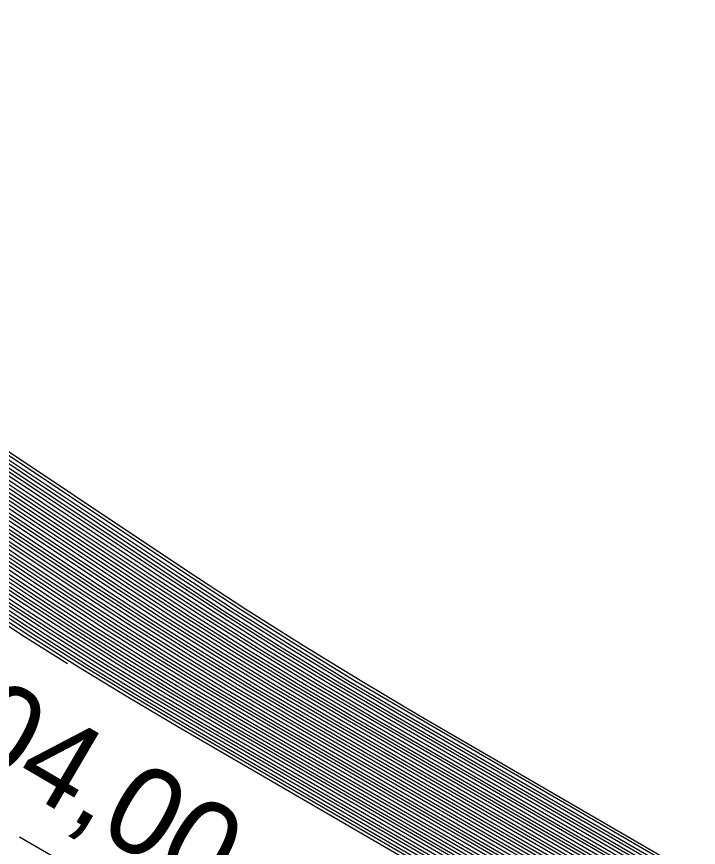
# Model space of a CAD drawing. Extents: x -500397 to -496810, y -1135552 to -1132176.
# Drawn here: x -500370.44 to -500354.9, y -1134753.02 to -1134734.1 of the extents above; entities that cross this region are included whole.
import ezdxf

# ---------------------------------------------------------------- set-up
doc = ezdxf.new("R2010")
doc.units = 0
doc.layers.add('30', color=7, linetype='Continuous')
doc.layers.add('40', color=7, linetype='Continuous')

msp = doc.modelspace()

# ---------------------------------------------------------------- linework, layer by layer
at = {"layer": '30'}
for points in [[(-500380.743, -1134693.182), (-500385.671, -1134735.388), (-500385.641, -1134736.758), (-500385.201, -1134737.849), (-500384.35, -1134738.663), (-500383.089, -1134739.197), (-500377.22, -1134740.779), (-500375.778, -1134741.23), (-500374.387, -1134741.793), (-500373.046, -1134742.468), (-500371.756, -1134743.254), (-500366.516, -1134746.742), (-500365.215, -1134747.594), (-500363.901, -1134748.426), (-500362.574, -1134749.237), (-500361.235, -1134750.028), (-500343.499, -1134760.322)], [(-500343.695, -1134760.29), (-500361.367, -1134750.034), (-500362.701, -1134749.246), (-500364.023, -1134748.437), (-500365.332, -1134747.609), (-500366.628, -1134746.76), (-500371.849, -1134743.284), (-500373.135, -1134742.501), (-500374.471, -1134741.829), (-500375.857, -1134741.268), (-500377.294, -1134740.818), (-500383.141, -1134739.242), (-500384.398, -1134738.71), (-500385.246, -1134737.9), (-500385.684, -1134736.812), (-500385.713, -1134735.447), (-500382.293, -1134706.144)], [(-500382.833, -1134710.461), (-500385.756, -1134735.506), (-500385.727, -1134736.866), (-500385.29, -1134737.95), (-500384.446, -1134738.757), (-500383.193, -1134739.288), (-500377.367, -1134740.858), (-500375.936, -1134741.306), (-500374.555, -1134741.865), (-500373.224, -1134742.534), (-500371.943, -1134743.315), (-500366.741, -1134746.778), (-500365.449, -1134747.623), (-500364.145, -1134748.449), (-500362.828, -1134749.254), (-500361.498, -1134750.04), (-500343.892, -1134760.258)], [(-500344.088, -1134760.227), (-500361.63, -1134750.045), (-500362.955, -1134749.263), (-500364.267, -1134748.46), (-500365.566, -1134747.638), (-500366.853, -1134746.795), (-500372.036, -1134743.345), (-500373.312, -1134742.567), (-500374.638, -1134741.9), (-500376.015, -1134741.343), (-500377.441, -1134740.897), (-500383.245, -1134739.333), (-500384.493, -1134738.804), (-500385.335, -1134738), (-500385.77, -1134736.92), (-500385.799, -1134735.565), (-500383.373, -1134714.779)], [(-500385.839, -1134735.757), (-500385.813, -1134736.974), (-500385.38, -1134738.05), (-500384.541, -1134738.851), (-500383.298, -1134739.378), (-500377.514, -1134740.937), (-500376.094, -1134741.381), (-500374.722, -1134741.936), (-500373.401, -1134742.601), (-500372.13, -1134743.375), (-500366.966, -1134746.813), (-500365.684, -1134747.653), (-500364.389, -1134748.472), (-500363.082, -1134749.272), (-500361.762, -1134750.051), (-500344.284, -1134760.195)], [(-500344.48, -1134760.163), (-500361.894, -1134750.057), (-500363.209, -1134749.28), (-500364.511, -1134748.484), (-500365.801, -1134747.667), (-500367.079, -1134746.831), (-500372.223, -1134743.406), (-500373.49, -1134742.634), (-500374.806, -1134741.972), (-500376.172, -1134741.419), (-500377.588, -1134740.976), (-500383.35, -1134739.423), (-500384.589, -1134738.898), (-500385.424, -1134738.1), (-500385.856, -1134737.028), (-500385.875, -1134736.143)], [(-500344.677, -1134760.132), (-500362.026, -1134750.063), (-500363.335, -1134749.289), (-500364.633, -1134748.495), (-500365.918, -1134747.682), (-500367.191, -1134746.849), (-500372.317, -1134743.436), (-500373.579, -1134742.667), (-500374.89, -1134742.007), (-500376.251, -1134741.457), (-500377.662, -1134741.015), (-500383.402, -1134739.468), (-500384.637, -1134738.945), (-500385.469, -1134738.15), (-500385.899, -1134737.082), (-500385.911, -1134736.529)], [(-500385.947, -1134736.915), (-500385.942, -1134737.136), (-500385.514, -1134738.2), (-500384.684, -1134738.992), (-500383.455, -1134739.513), (-500377.735, -1134741.055), (-500376.33, -1134741.495), (-500374.974, -1134742.043), (-500373.668, -1134742.701), (-500372.41, -1134743.467), (-500367.304, -1134746.866), (-500366.036, -1134747.696), (-500364.755, -1134748.507), (-500363.462, -1134749.298), (-500362.157, -1134750.068), (-500344.873, -1134760.1)], [(-500385.975, -1134737.216), (-500385.558, -1134738.25), (-500384.732, -1134739.04), (-500383.507, -1134739.559), (-500377.809, -1134741.094), (-500376.409, -1134741.532), (-500375.058, -1134742.079), (-500373.756, -1134742.734), (-500372.504, -1134743.497), (-500367.416, -1134746.884), (-500366.153, -1134747.711), (-500364.877, -1134748.519), (-500363.589, -1134749.306), (-500362.289, -1134750.074), (-500345.069, -1134760.068)], [(-500345.265, -1134760.037), (-500362.421, -1134750.08), (-500363.716, -1134749.315), (-500364.999, -1134748.53), (-500366.27, -1134747.726), (-500367.529, -1134746.902), (-500372.597, -1134743.528), (-500373.845, -1134742.767), (-500375.142, -1134742.115), (-500376.488, -1134741.57), (-500377.883, -1134741.134), (-500383.559, -1134739.604), (-500384.78, -1134739.087), (-500385.603, -1134738.3), (-500385.987, -1134737.346)], [(-500386.012, -1134737.608), (-500385.692, -1134738.4), (-500384.875, -1134739.181), (-500383.664, -1134739.694), (-500378.03, -1134741.213), (-500376.646, -1134741.646), (-500375.31, -1134742.186), (-500374.023, -1134742.834), (-500372.784, -1134743.588), (-500367.754, -1134746.937), (-500366.505, -1134747.755), (-500365.243, -1134748.553), (-500363.97, -1134749.332), (-500362.684, -1134750.092), (-500345.658, -1134759.974)], [(-500385.999, -1134737.477), (-500385.647, -1134738.35), (-500384.827, -1134739.134), (-500383.612, -1134739.649), (-500377.956, -1134741.173), (-500376.567, -1134741.608), (-500375.226, -1134742.15), (-500373.934, -1134742.8), (-500372.691, -1134743.558), (-500367.641, -1134746.919), (-500366.387, -1134747.74), (-500365.121, -1134748.542), (-500363.843, -1134749.324), (-500362.553, -1134750.086), (-500345.462, -1134760.005)], [(-500345.854, -1134759.942), (-500362.816, -1134750.097), (-500364.097, -1134749.341), (-500365.365, -1134748.565), (-500366.622, -1134747.77), (-500367.867, -1134746.955), (-500372.878, -1134743.619), (-500374.112, -1134742.867), (-500375.394, -1134742.222), (-500376.725, -1134741.684), (-500378.104, -1134741.252), (-500383.716, -1134739.739), (-500384.923, -1134739.228), (-500385.737, -1134738.45), (-500386.024, -1134737.738)], [(-500346.051, -1134759.91), (-500362.948, -1134750.103), (-500364.224, -1134749.35), (-500365.488, -1134748.577), (-500366.739, -1134747.784), (-500367.979, -1134746.973), (-500372.971, -1134743.649), (-500374.201, -1134742.9), (-500375.478, -1134742.258), (-500376.803, -1134741.721), (-500378.177, -1134741.291), (-500383.768, -1134739.785), (-500384.971, -1134739.275), (-500385.781, -1134738.5), (-500386.036, -1134737.869)], [(-500386.06, -1134738.13), (-500385.87, -1134738.601), (-500385.066, -1134739.369), (-500383.873, -1134739.875), (-500378.324, -1134741.37), (-500376.961, -1134741.797), (-500375.646, -1134742.329), (-500374.378, -1134742.967), (-500373.158, -1134743.71), (-500368.204, -1134747.008), (-500366.974, -1134747.814), (-500365.732, -1134748.6), (-500364.478, -1134749.367), (-500363.211, -1134750.115), (-500346.443, -1134759.847)], [(-500346.247, -1134759.879), (-500363.08, -1134750.109), (-500364.351, -1134749.358), (-500365.61, -1134748.588), (-500366.857, -1134747.799), (-500368.092, -1134746.99), (-500373.065, -1134743.68), (-500374.289, -1134742.934), (-500375.562, -1134742.293), (-500376.882, -1134741.759), (-500378.251, -1134741.331), (-500383.821, -1134739.83), (-500385.018, -1134739.322), (-500385.826, -1134738.551), (-500386.048, -1134737.999)], [(-500346.639, -1134759.815), (-500363.343, -1134750.121), (-500364.604, -1134749.376), (-500365.854, -1134748.611), (-500367.091, -1134747.828), (-500368.317, -1134747.026), (-500373.252, -1134743.741), (-500374.467, -1134743), (-500375.73, -1134742.365), (-500377.04, -1134741.835), (-500378.398, -1134741.41), (-500383.925, -1134739.92), (-500385.114, -1134739.416), (-500385.915, -1134738.651), (-500386.072, -1134738.261)], [(-500386.097, -1134738.522), (-500386.004, -1134738.751), (-500385.209, -1134739.511), (-500384.03, -1134740.01), (-500378.545, -1134741.489), (-500377.198, -1134741.91), (-500375.898, -1134742.436), (-500374.645, -1134743.067), (-500373.439, -1134743.801), (-500368.542, -1134747.061), (-500367.326, -1134747.858), (-500366.098, -1134748.635), (-500364.858, -1134749.393), (-500363.607, -1134750.132), (-500347.032, -1134759.752)], [(-500346.836, -1134759.784), (-500363.475, -1134750.126), (-500364.731, -1134749.384), (-500365.976, -1134748.623), (-500367.208, -1134747.843), (-500368.429, -1134747.044), (-500373.345, -1134743.771), (-500374.556, -1134743.033), (-500375.814, -1134742.401), (-500377.119, -1134741.872), (-500378.472, -1134741.449), (-500383.978, -1134739.965), (-500385.161, -1134739.464), (-500385.96, -1134738.701), (-500386.084, -1134738.391)], [(-500386.109, -1134738.652), (-500386.049, -1134738.801), (-500385.257, -1134739.558), (-500384.082, -1134740.056), (-500378.619, -1134741.528), (-500377.277, -1134741.948), (-500375.982, -1134742.472), (-500374.733, -1134743.1), (-500373.532, -1134743.832), (-500368.654, -1134747.079), (-500367.443, -1134747.872), (-500366.22, -1134748.646), (-500364.985, -1134749.402), (-500363.738, -1134750.138), (-500347.228, -1134759.72)], [(-500347.621, -1134759.657), (-500364.002, -1134750.15), (-500365.239, -1134749.419), (-500366.464, -1134748.67), (-500367.678, -1134747.901), (-500368.88, -1134747.115), (-500373.719, -1134743.893), (-500374.911, -1134743.167), (-500376.149, -1134742.543), (-500377.434, -1134742.024), (-500378.766, -1134741.607), (-500384.187, -1134740.146), (-500385.352, -1134739.652), (-500386.132, -1134738.906)], [(-500347.424, -1134759.689), (-500363.87, -1134750.144), (-500365.112, -1134749.41), (-500366.342, -1134748.658), (-500367.56, -1134747.887), (-500368.767, -1134747.097), (-500373.626, -1134743.862), (-500374.822, -1134743.133), (-500376.065, -1134742.508), (-500377.356, -1134741.986), (-500378.693, -1134741.567), (-500384.134, -1134740.101), (-500385.304, -1134739.605), (-500386.093, -1134738.851), (-500386.121, -1134738.783)], [(-500348.013, -1134759.594), (-500364.266, -1134750.161), (-500365.493, -1134749.436), (-500366.708, -1134748.693), (-500367.912, -1134747.931), (-500369.105, -1134747.15), (-500373.906, -1134743.954), (-500375.089, -1134743.233), (-500376.317, -1134742.615), (-500377.592, -1134742.099), (-500378.914, -1134741.686), (-500384.291, -1134740.236), (-500385.448, -1134739.746), (-500386.148, -1134739.077)], [(-500386.14, -1134738.992), (-500385.4, -1134739.699), (-500384.239, -1134740.191), (-500378.84, -1134741.646), (-500377.513, -1134742.061), (-500376.233, -1134742.579), (-500375, -1134743.2), (-500373.813, -1134743.923), (-500368.992, -1134747.132), (-500367.795, -1134747.916), (-500366.586, -1134748.681), (-500365.366, -1134749.428), (-500364.134, -1134750.155), (-500347.817, -1134759.625)], [(-500386.164, -1134739.247), (-500385.543, -1134739.841), (-500384.396, -1134740.327), (-500379.061, -1134741.764), (-500377.75, -1134742.175), (-500376.485, -1134742.686), (-500375.266, -1134743.3), (-500374.093, -1134744.014), (-500369.33, -1134747.186), (-500368.147, -1134747.96), (-500366.952, -1134748.716), (-500365.746, -1134749.454), (-500364.529, -1134750.173), (-500348.406, -1134759.531)], [(-500386.156, -1134739.162), (-500385.495, -1134739.793), (-500384.344, -1134740.281), (-500378.987, -1134741.725), (-500377.671, -1134742.137), (-500376.401, -1134742.651), (-500375.177, -1134743.266), (-500374, -1134743.984), (-500369.217, -1134747.168), (-500368.03, -1134747.945), (-500366.83, -1134748.704), (-500365.62, -1134749.445), (-500364.397, -1134750.167), (-500348.209, -1134759.562)], [(-500348.994, -1134759.436), (-500364.924, -1134750.19), (-500366.127, -1134749.48), (-500367.319, -1134748.751), (-500368.499, -1134748.004), (-500369.667, -1134747.239), (-500374.374, -1134744.106), (-500375.533, -1134743.399), (-500376.737, -1134742.794), (-500377.987, -1134742.288), (-500379.282, -1134741.883), (-500384.553, -1134740.462), (-500385.686, -1134739.982), (-500386.188, -1134739.502)], [(-500348.798, -1134759.467), (-500364.793, -1134750.184), (-500366, -1134749.471), (-500367.197, -1134748.739), (-500368.381, -1134747.989), (-500369.555, -1134747.221), (-500374.28, -1134744.075), (-500375.444, -1134743.366), (-500376.653, -1134742.758), (-500377.908, -1134742.25), (-500379.208, -1134741.843), (-500384.501, -1134740.417), (-500385.638, -1134739.935), (-500386.18, -1134739.417)], [(-500386.172, -1134739.332), (-500385.591, -1134739.888), (-500384.448, -1134740.372), (-500379.134, -1134741.804), (-500377.829, -1134742.212), (-500376.569, -1134742.722), (-500375.355, -1134743.333), (-500374.187, -1134744.045), (-500369.442, -1134747.203), (-500368.264, -1134747.975), (-500367.074, -1134748.728), (-500365.873, -1134749.462), (-500364.661, -1134750.178), (-500348.602, -1134759.499)], [(-500386.204, -1134739.673), (-500385.782, -1134740.076), (-500384.657, -1134740.552), (-500379.429, -1134741.962), (-500378.144, -1134742.364), (-500376.905, -1134742.865), (-500375.71, -1134743.466), (-500374.561, -1134744.166), (-500369.893, -1134747.274), (-500368.733, -1134748.033), (-500367.563, -1134748.774), (-500366.381, -1134749.497), (-500365.188, -1134750.202), (-500349.387, -1134759.372)], [(-500386.196, -1134739.588), (-500385.734, -1134740.029), (-500384.605, -1134740.507), (-500379.355, -1134741.922), (-500378.066, -1134742.326), (-500376.821, -1134742.829), (-500375.622, -1134743.433), (-500374.467, -1134744.136), (-500369.78, -1134747.256), (-500368.616, -1134748.019), (-500367.441, -1134748.762), (-500366.254, -1134749.488), (-500365.056, -1134750.196), (-500349.191, -1134759.404)], [(-500386.22, -1134739.843), (-500385.877, -1134740.17), (-500384.762, -1134740.643), (-500379.576, -1134742.04), (-500378.302, -1134742.439), (-500377.073, -1134742.937), (-500375.888, -1134743.533), (-500374.748, -1134744.227), (-500370.118, -1134747.31), (-500368.968, -1134748.062), (-500367.807, -1134748.797), (-500366.635, -1134749.514), (-500365.451, -1134750.213), (-500349.779, -1134759.309)], [(-500386.212, -1134739.758), (-500385.829, -1134740.123), (-500384.71, -1134740.598), (-500379.503, -1134742.001), (-500378.223, -1134742.401), (-500376.989, -1134742.901), (-500375.799, -1134743.499), (-500374.654, -1134744.197), (-500370.005, -1134747.292), (-500368.851, -1134748.048), (-500367.685, -1134748.786), (-500366.508, -1134749.506), (-500365.32, -1134750.207), (-500349.583, -1134759.341)], [(-500386.228, -1134739.928), (-500385.925, -1134740.217), (-500384.814, -1134740.688), (-500379.65, -1134742.08), (-500378.381, -1134742.477), (-500377.157, -1134742.972), (-500375.977, -1134743.566), (-500374.841, -1134744.258), (-500370.23, -1134747.327), (-500369.085, -1134748.077), (-500367.929, -1134748.809), (-500366.762, -1134749.523), (-500365.583, -1134750.219), (-500349.976, -1134759.277)], [(-500350.172, -1134759.246), (-500365.715, -1134750.225), (-500366.888, -1134749.532), (-500368.051, -1134748.821), (-500369.202, -1134748.092), (-500370.343, -1134747.345), (-500374.935, -1134744.288), (-500376.066, -1134743.599), (-500377.241, -1134743.008), (-500378.46, -1134742.515), (-500379.724, -1134742.119), (-500383.186, -1134741.186)], [(-500350.368, -1134759.214), (-500365.847, -1134750.231), (-500367.015, -1134749.54), (-500368.173, -1134748.832), (-500369.32, -1134748.106), (-500370.455, -1134747.363), (-500375.028, -1134744.319), (-500376.154, -1134743.632), (-500377.325, -1134743.044), (-500378.539, -1134742.552), (-500379.797, -1134742.159), (-500382.941, -1134741.311)], [(-500382.695, -1134741.437), (-500379.871, -1134742.198), (-500378.618, -1134742.59), (-500377.408, -1134743.079), (-500376.243, -1134743.666), (-500375.122, -1134744.349), (-500370.568, -1134747.381), (-500369.437, -1134748.121), (-500368.295, -1134748.844), (-500367.142, -1134749.549), (-500365.978, -1134750.236), (-500350.564, -1134759.183)], [(-500382.45, -1134741.562), (-500379.944, -1134742.238), (-500378.697, -1134742.628), (-500377.492, -1134743.115), (-500376.332, -1134743.699), (-500375.215, -1134744.379), (-500370.681, -1134747.398), (-500369.554, -1134748.136), (-500368.417, -1134748.855), (-500367.269, -1134749.558), (-500366.11, -1134750.242), (-500350.761, -1134759.151)], [(-500350.957, -1134759.119), (-500366.242, -1134750.248), (-500367.396, -1134749.566), (-500368.539, -1134748.867), (-500369.672, -1134748.15), (-500370.793, -1134747.416), (-500375.309, -1134744.41), (-500376.421, -1134743.732), (-500377.576, -1134743.151), (-500378.775, -1134742.666), (-500380.018, -1134742.277), (-500382.205, -1134741.688)], [(-500381.96, -1134741.813), (-500380.092, -1134742.316), (-500378.854, -1134742.704), (-500377.66, -1134743.187), (-500376.51, -1134743.766), (-500375.403, -1134744.44), (-500370.906, -1134747.434), (-500369.789, -1134748.165), (-500368.661, -1134748.879), (-500367.523, -1134749.575), (-500366.374, -1134750.254), (-500351.153, -1134759.088)], [(-500381.714, -1134741.938), (-500380.165, -1134742.356), (-500378.933, -1134742.741), (-500377.744, -1134743.222), (-500376.599, -1134743.799), (-500375.496, -1134744.471), (-500371.018, -1134747.452), (-500369.906, -1134748.18), (-500368.783, -1134748.89), (-500367.65, -1134749.584), (-500366.505, -1134750.26), (-500351.349, -1134759.056)], [(-500351.546, -1134759.024), (-500366.637, -1134750.265), (-500367.777, -1134749.592), (-500368.906, -1134748.902), (-500370.024, -1134748.194), (-500371.131, -1134747.469), (-500375.59, -1134744.501), (-500376.687, -1134743.832), (-500377.828, -1134743.258), (-500379.012, -1134742.779), (-500380.239, -1134742.395), (-500381.469, -1134742.064)], [(-500351.742, -1134758.993), (-500366.769, -1134750.271), (-500367.904, -1134749.601), (-500369.028, -1134748.913), (-500370.141, -1134748.209), (-500371.243, -1134747.487), (-500375.683, -1134744.532), (-500376.776, -1134743.865), (-500377.912, -1134743.294), (-500379.091, -1134742.817), (-500380.313, -1134742.435), (-500381.224, -1134742.189)], [(-500369.281, -1134748.842), (-500370.258, -1134748.224), (-500371.356, -1134747.505), (-500372.613, -1134746.668)], [(-500366.579, -1134754.988), (-500370.376, -1134752.784)]]:
    msp.add_lwpolyline(points, dxfattribs=at)

# ---------------------------------------------------------------- texts
at = {"layer": '40'}
msp.add_text('204,00', height=2, rotation=329.6235, dxfattribs=at).set_placement((-500373.137, -1134750.059))

doc.saveas('drawing.dxf')
